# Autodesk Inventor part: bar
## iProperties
Author: Rich
Shininess: 20.0
PropertySet Name: _Private Model Information
Created: 2001-04
Part Number: bar
Document SubType Name: Modeling
Designer: Rich
Control State: 0
Master: False
Checked Out: False
PropertySet Name: Design Tracking Control
Density: 0.0
Volumn: 0.0
Area: 0.0
PropertySet Name: Model Information
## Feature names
1. Sweep1
